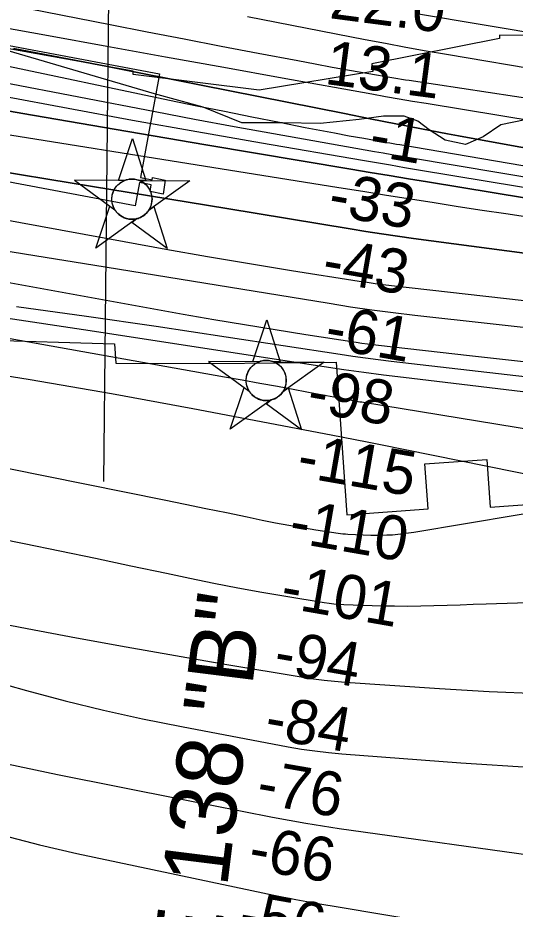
# Model space of a CAD drawing. Extents: x 3508733 to 3546731, y 546897 to 572481.
# Drawn here: x 3524097 to 3524852, y 564701 to 566055 of the extents above; entities that cross this region are included whole.
import ezdxf

# ---------------------------------------------------------------- set-up
doc = ezdxf.new("R2010")
doc.units = 0
for name, color, linetype in [('V-CHAN-DOCK', 7, 'Continuous'), ('V-CHAN-NAID', 7, 'Continuous'), ('V-RIVR-EDGE', 7, 'Continuous'), ('V-RIVR-RANG', 7, 'Continuous'), ('V-RRAP-RVMT', 7, 'Continuous'), ('V-TOPO-DPTH', 7, 'Continuous'), ('V-TOPO-MAJR', 7, 'Continuous'), ('V-TOPO-MINR', 7, 'Continuous'), ('V-TOPO-WATR', 7, 'Continuous')]:
    doc.layers.add(name, color=color, linetype=linetype)

msp = doc.modelspace()

# ---------------------------------------------------------------- linework, layer by layer
at = {"layer": 'V-CHAN-DOCK'}
for points in [[(3523879.2, 566051.2), (3524312, 565969.5), (3524282.8, 565812.2), (3524282.8, 565812.2)], [(3524282.8, 565812.2), (3524300.6, 565808.9), (3524301.1, 565812), (3524320.5, 565808.2), (3524317.3, 565786.7), (3524297.5, 565790.7), (3524299.3, 565801), (3524281.4, 565804.4), (3524281.4, 565804.4), (3524274.9, 565769.4), (3523635.2, 565889.5)]]:
    msp.add_lwpolyline(points, dxfattribs=at)
at = {"layer": 'V-CHAN-NAID'}
for points in [[(3524259.1, 565807.8), (3524249.5, 565807.9), (3524270.7, 565871.4), (3524290.9, 565807.6), (3524281.3, 565807.6), (3524279.7, 565808.2), (3524277.6, 565808.8), (3524275.6, 565809.3), (3524273.6, 565809.6), (3524272.4, 565809.7), (3524270.9, 565809.8), (3524269.1, 565809.8), (3524267.8, 565809.7), (3524265.9, 565809.5), (3524264.5, 565809.3), (3524262.7, 565808.9), (3524261.2, 565808.5), (3524260.1, 565808.2)], [(3524259.1, 565807.8), (3524182.6, 565808.3), (3524244.2, 565762.9), (3524243.1, 565764.9), (3524242.3, 565766.5), (3524241.5, 565768.4), (3524240.8, 565770.5), (3524240.4, 565771.8), (3524240, 565773.4), (3524239.8, 565774.9), (3524239.6, 565776.5), (3524239.5, 565778.2), (3524239.5, 565779.8), (3524239.6, 565781.9), (3524239.8, 565783.5), (3524240.2, 565785.7), (3524240.6, 565787.6), (3524241.2, 565789.5), (3524241.9, 565791.2), (3524242.6, 565792.8), (3524243.4, 565794.3), (3524244.5, 565796.1), (3524245.5, 565797.5), (3524246.5, 565798.8), (3524247.5, 565799.9), (3524248.8, 565801.3), (3524249.9, 565802.2), (3524251.6, 565803.6), (3524252.8, 565804.5), (3524254.5, 565805.6), (3524256.2, 565806.5), (3524257.7, 565807.2)], [(3524281.3, 565807.6), (3524357.8, 565807.1), (3524295.6, 565762.6), (3524296.5, 565764.1), (3524297.5, 565765.9), (3524298.2, 565767.5), (3524298.9, 565769.5), (3524299.5, 565771.2), (3524299.9, 565772.9), (3524300.2, 565774.9), (3524300.4, 565776.5), (3524300.6, 565778.7), (3524300.5, 565780.7), (3524300.3, 565782.9), (3524300.1, 565784.7), (3524299.6, 565786.9), (3524298.9, 565789.1), (3524298.2, 565791.1), (3524297.5, 565792.5), (3524296.5, 565794.4), (3524295.5, 565796.1), (3524294.3, 565797.8), (3524293, 565799.4), (3524291.7, 565800.7), (3524290.1, 565802.3), (3524288.3, 565803.7), (3524286.7, 565804.9), (3524284.8, 565806), (3524283.3, 565806.8)], [(3524277.6, 565749.7), (3524215.4, 565705.1), (3524236.5, 565768.6), (3524244.2, 565762.9), (3524244.8, 565762), (3524246.2, 565760.1), (3524247.4, 565758.7), (3524248.9, 565757.2), (3524250.3, 565755.9), (3524251.7, 565754.8), (3524253.1, 565753.8), (3524254.8, 565752.8), (3524256.5, 565751.9), (3524258.3, 565751), (3524259.8, 565750.5), (3524261.4, 565750), (3524263.6, 565749.4), (3524265.2, 565749.1), (3524267.2, 565748.9), (3524268.7, 565748.8), (3524270.6, 565748.7), (3524272.3, 565748.8), (3524274, 565749), (3524275.9, 565749.3)], [(3524295.6, 565762.6), (3524303.4, 565768.2), (3524323.6, 565704.4), (3524269.8, 565744.1), (3524277.6, 565749.7), (3524279.2, 565750.1), (3524280.8, 565750.7), (3524283, 565751.6), (3524284.7, 565752.5), (3524286.6, 565753.6), (3524288.3, 565754.8), (3524289.9, 565756.1), (3524291.2, 565757.2), (3524292.6, 565758.7), (3524293.8, 565760.1), (3524294.9, 565761.5)], [(3524462.9, 565532.4), (3524453.3, 565532.5), (3524474.5, 565596), (3524494.7, 565532.2), (3524485.1, 565532.3), (3524483.5, 565532.8), (3524481.4, 565533.5), (3524479.4, 565533.9), (3524477.3, 565534.2), (3524476.2, 565534.3), (3524474.6, 565534.4), (3524472.9, 565534.4), (3524471.6, 565534.4), (3524469.6, 565534.1), (3524468.3, 565533.9), (3524466.5, 565533.5), (3524465, 565533.1), (3524463.9, 565532.8)], [(3524462.9, 565532.4), (3524386.4, 565533), (3524448, 565487.6), (3524446.9, 565489.5), (3524446.1, 565491.1), (3524445.2, 565493.1), (3524444.6, 565495.1), (3524444.2, 565496.5), (3524443.8, 565498.1), (3524443.6, 565499.5), (3524443.4, 565501.1), (3524443.3, 565502.9), (3524443.3, 565504.4), (3524443.4, 565506.5), (3524443.6, 565508.1), (3524444, 565510.3), (3524444.4, 565512.3), (3524445, 565514.1), (3524445.7, 565515.8), (3524446.4, 565517.4), (3524447.2, 565518.9), (3524448.3, 565520.7), (3524449.3, 565522.2), (3524450.3, 565523.4), (3524451.3, 565524.6), (3524452.6, 565525.9), (3524453.7, 565526.9), (3524455.4, 565528.3), (3524456.6, 565529.1), (3524458.3, 565530.2), (3524460, 565531.2), (3524461.5, 565531.8)], [(3524485.1, 565532.3), (3524561.6, 565531.7), (3524499.4, 565487.2), (3524500.3, 565488.7), (3524501.3, 565490.5), (3524502, 565492.1), (3524502.7, 565494.1), (3524503.3, 565495.9), (3524503.7, 565497.5), (3524504, 565499.5), (3524504.2, 565501.1), (3524504.3, 565503.3), (3524504.3, 565505.4), (3524504.1, 565507.6), (3524503.9, 565509.3), (3524503.4, 565511.6), (3524502.7, 565513.7), (3524502, 565515.7), (3524501.3, 565517.1), (3524500.3, 565519), (3524499.3, 565520.8), (3524498, 565522.5), (3524496.8, 565524), (3524495.5, 565525.4), (3524493.9, 565526.9), (3524492.1, 565528.3), (3524490.5, 565529.5), (3524488.6, 565530.6), (3524487.1, 565531.4)], [(3524481.4, 565474.3), (3524419.2, 565429.8), (3524440.3, 565493.3), (3524448, 565487.6), (3524448.6, 565486.6), (3524450, 565484.7), (3524451.2, 565483.3), (3524452.7, 565481.8), (3524454.1, 565480.6), (3524455.5, 565479.4), (3524456.9, 565478.4), (3524458.6, 565477.4), (3524460.3, 565476.5), (3524462.1, 565475.7), (3524463.6, 565475.1), (3524465.2, 565474.6), (3524467.4, 565474), (3524469, 565473.7), (3524471, 565473.5), (3524472.5, 565473.4), (3524474.4, 565473.4), (3524476.1, 565473.4), (3524477.8, 565473.6), (3524479.7, 565473.9)], [(3524499.4, 565487.2), (3524507.2, 565492.8), (3524527.4, 565429), (3524473.6, 565468.7), (3524481.4, 565474.3), (3524483, 565474.8), (3524484.6, 565475.3), (3524486.8, 565476.2), (3524488.5, 565477.1), (3524490.4, 565478.2), (3524492.1, 565479.5), (3524493.7, 565480.7), (3524495, 565481.9), (3524496.4, 565483.3), (3524497.6, 565484.7), (3524498.7, 565486.2)]]:
    msp.add_lwpolyline(points, close=True, dxfattribs=at)
for centre in [(3524270, 565779.3), (3524473.8, 565503.9)]:
    msp.add_circle(centre, 30.5, dxfattribs=at)
at = {"layer": 'V-RIVR-EDGE'}
msp.add_lwpolyline([(3524866.8, 565900), (3524830, 565892.2), (3524803, 565873.9), (3524776, 565862.3), (3524745.4, 565869.1), (3524721, 565884.5), (3524703.8, 565898), (3524683, 565905.4), (3524651.8, 565905.5), (3524615, 565900.1), (3524555.5, 565894.1), (3524498.6, 565895.4), (3524436.7, 565895), (3524377.9, 565919), (3524304.4, 565939.4), (3524064.4, 566009.9)], dxfattribs=at)
at = {"layer": 'V-RIVR-RANG'}
msp.add_line((3524237, 566350.7), (3524226.6, 565350.7), dxfattribs=at)
at = {"layer": 'V-RRAP-RVMT'}
for points in [[(3524827.9, 566028.5), (3524827.9, 566023.4), (3524634, 565985), (3524635.4, 565973.3), (3524463.2, 565944.8), (3524271.9, 565968.7), (3524271.9, 565973.6), (3524074.8, 566009.4)], [(3526258.3, 565752.8), (3526053.8, 565759.9), (3526054, 565771.3), (3525840.3, 565785.2), (3525840.4, 565782.7), (3525643.5, 565821.3), (3525642.9, 565837.2), (3525438.8, 565876.6), (3525439.3, 565914.1), (3525237.3, 565952.4), (3525238.2, 565977.9), (3525037.5, 566014.9), (3525037.3, 566027), (3524827.9, 566028.5)], [(3524038.9, 565565.7), (3524243.4, 565559.8), (3524245.6, 565530.1), (3524394.8, 565529.7), (3524579.8, 565531.5)], [(3524579.8, 565531.5), (3524596, 565300), (3524719.8, 565308.8), (3524714.7, 565377.5), (3524808.7, 565384), (3524813.6, 565311.3), (3524953.5, 565321.4)]]:
    msp.add_lwpolyline(points, dxfattribs=at)
at = {"layer": 'V-TOPO-DPTH'}
for points in [[(3525130.5, 565892.5), (3524690.7, 565959.3), (3524685, 565960.2), (3524679.2, 565961.1), (3524673.5, 565962), (3524667.7, 565963), (3524626.6, 565970.2), (3524600.4, 565974.8), (3524574.1, 565979.5), (3524547.9, 565984.3), (3524521.6, 565989.2), (3524461.7, 566000.6), (3524405.5, 566011.4), (3524349.3, 566022.2), (3524293.2, 566033.1), (3524237.1, 566044.2), (3523968, 566097.4)], [(3524090.1, 566008.2), (3524232.7, 565980.7), (3524375.2, 565952.6), (3524592.4, 565909.2), (3524631.5, 565901.4), (3524670.6, 565893.8), (3524709.7, 565886.2), (3524748.8, 565878.7), (3524765.4, 565875.5), (3524812.9, 565866.7), (3524860.4, 565858.2), (3524908, 565850.3), (3524955.7, 565842.6), (3525771.7, 565716.3), (3525806.4, 565711.2), (3525841, 565706.3), (3525875.8, 565701.8), (3525910.6, 565697.6), (3526934.8, 565580.1)], [(3524090.1, 566008.2), (3524232.7, 565980.7), (3524375.2, 565952.6), (3524592.4, 565909.2), (3524631.5, 565901.4), (3524670.6, 565893.8), (3524709.7, 565886.2), (3524748.8, 565878.7), (3524765.4, 565875.5), (3524812.9, 565866.7), (3524860.4, 565858.2), (3524908, 565850.3), (3524955.7, 565842.6), (3525771.7, 565716.3), (3525806.4, 565711.2), (3525841, 565706.3), (3525875.8, 565701.8), (3525910.6, 565697.6), (3526934.8, 565580.1)], [(3526199.5, 565611.7), (3526108.1, 565622.7), (3526016.7, 565633.7), (3525854.1, 565653.3), (3525844, 565654.6), (3525833.8, 565655.9), (3525823.7, 565657.3), (3525813.6, 565658.8), (3525680.8, 565678.7), (3525604.4, 565690.4), (3525527.9, 565702.3), (3525451.6, 565714.7), (3525375.3, 565727.3), (3524691, 565842.3), (3524677.7, 565844.5), (3524664.5, 565846.8), (3524651.2, 565849.1), (3524638, 565851.4), (3524544.6, 565867.7), (3524484.7, 565878.3), (3524424.9, 565889.1), (3524365.1, 565900.3), (3524305.3, 565911.7), (3524073.4, 565956.4)], [(3526199.5, 565611.7), (3526108.1, 565622.7), (3526016.7, 565633.7), (3525854.1, 565653.3), (3525844, 565654.6), (3525833.8, 565655.9), (3525823.7, 565657.3), (3525813.6, 565658.8), (3525680.8, 565678.7), (3525604.4, 565690.4), (3525527.9, 565702.3), (3525451.6, 565714.7), (3525375.3, 565727.3), (3524691, 565842.3), (3524677.7, 565844.5), (3524664.5, 565846.8), (3524651.2, 565849.1), (3524638, 565851.4), (3524544.6, 565867.7), (3524484.7, 565878.3), (3524424.9, 565889.1), (3524365.1, 565900.3), (3524305.3, 565911.7), (3524073.4, 565956.4)], [(3523965.3, 565933.5), (3524104.2, 565909.3), (3524243.2, 565885.4), (3524382.2, 565861.8), (3524602.2, 565824.7), (3524631.3, 565819.8), (3524660.4, 565815), (3524689.5, 565810.2), (3524718.6, 565805.4), (3524918, 565772.9), (3525046.9, 565752.2), (3525175.8, 565731.9), (3525304.8, 565712.1), (3525433.9, 565692.7), (3525788.5, 565640.1), (3525809.6, 565637), (3525830.7, 565634.1), (3525851.8, 565631.3), (3525872.9, 565628.6), (3526418, 565561.4)], [(3523965.3, 565933.5), (3524104.2, 565909.3), (3524243.2, 565885.4), (3524382.2, 565861.8), (3524602.2, 565824.7), (3524631.3, 565819.8), (3524660.4, 565815), (3524689.5, 565810.2), (3524718.6, 565805.4), (3524918, 565772.9), (3525046.9, 565752.2), (3525175.8, 565731.9), (3525304.8, 565712.1), (3525433.9, 565692.7), (3525788.5, 565640.1), (3525809.6, 565637), (3525830.7, 565634.1), (3525851.8, 565631.3), (3525872.9, 565628.6), (3526418, 565561.4)], [(3526777.2, 565489.4), (3525892.5, 565602.7), (3525860, 565607), (3525827.5, 565611.4), (3525795, 565615.9), (3525762.5, 565620.6), (3524873.8, 565751.4), (3524837.6, 565756.8), (3524801.3, 565762.3), (3524765.1, 565767.9), (3524728.9, 565773.5), (3524692.7, 565779.2), (3524656.5, 565785), (3524620.3, 565790.7), (3524584.1, 565796.5), (3523856.5, 565912.8)], [(3526777.2, 565489.4), (3525892.5, 565602.7), (3525860, 565607), (3525827.5, 565611.4), (3525795, 565615.9), (3525762.5, 565620.6), (3524873.8, 565751.4), (3524837.6, 565756.8), (3524801.3, 565762.3), (3524765.1, 565767.9), (3524728.9, 565773.5), (3524692.7, 565779.2), (3524656.5, 565785), (3524620.3, 565790.7), (3524584.1, 565796.5), (3523856.5, 565912.8)], [(3524061.9, 565823), (3524179.4, 565803.7), (3524296.8, 565784.4), (3524414.2, 565765), (3524601, 565734), (3524625, 565730.2), (3524649, 565726.5), (3524673, 565723), (3524697.1, 565719.7), (3525623.5, 565596.8), (3525656.6, 565592.5), (3525689.6, 565588.4), (3525722.7, 565584.4), (3525755.8, 565580.6), (3525787.7, 565577.1), (3525804.8, 565575.1), (3525822, 565573.1), (3525839.1, 565571.1), (3525856.3, 565569.1), (3525873.4, 565567), (3525890.6, 565564.8), (3525907.7, 565562.6), (3525924.8, 565560.4), (3527000.1, 565416.8)], [(3524061.9, 565823), (3524179.4, 565803.7), (3524296.8, 565784.4), (3524414.2, 565765), (3524601, 565734), (3524625, 565730.2), (3524649, 565726.5), (3524673, 565723), (3524697.1, 565719.7), (3525623.5, 565596.8), (3525656.6, 565592.5), (3525689.6, 565588.4), (3525722.7, 565584.4), (3525755.8, 565580.6), (3525787.7, 565577.1), (3525804.8, 565575.1), (3525822, 565573.1), (3525839.1, 565571.1), (3525856.3, 565569.1), (3525873.4, 565567), (3525890.6, 565564.8), (3525907.7, 565562.6), (3525924.8, 565560.4), (3527000.1, 565416.8)]]:
    msp.add_lwpolyline(points, dxfattribs=at)
at = {"layer": 'V-TOPO-MAJR'}
for points in [[(3526752.2, 565406.9), (3525858.3, 565516.2), (3525836.4, 565518.9), (3525814.6, 565521.4), (3525792.7, 565523.9), (3525770.8, 565526.3), (3525317.9, 565574.9), (3525204.8, 565587.1), (3525091.6, 565599.5), (3524978.5, 565612.1), (3524865.4, 565624.8), (3524663.9, 565647.6), (3524651.5, 565649.1), (3524639.2, 565650.7), (3524626.9, 565652.5), (3524614.7, 565654.3), (3524512, 565670.7), (3524448.4, 565681.1), (3524384.9, 565691.8), (3524321.5, 565702.9), (3524258.1, 565714.3), (3523785.6, 565800.9)], [(3525548.4, 565318.8), (3524621.5, 565470.3), (3524618.8, 565470.8), (3524616.1, 565471.2), (3524613.4, 565471.7), (3524610.6, 565472.2), (3524593.5, 565475.4), (3524582.2, 565477.5), (3524570.9, 565479.6), (3524559.6, 565481.7), (3524548.4, 565483.8), (3524517.4, 565489.6), (3524490.7, 565494.6), (3524463.9, 565499.5), (3524437.2, 565504.4), (3524410.4, 565509.2), (3523835.7, 565611.6)], [(3523876, 565302.9), (3524106.6, 565256.1), (3524160.6, 565245), (3524214.6, 565233.9), (3524268.5, 565222.6), (3524322.5, 565211.2), (3524357.9, 565203.6), (3524394.1, 565196.2), (3524430.5, 565189.1), (3524466.9, 565182.5), (3524503.4, 565176.3), (3524561.8, 565166.7), (3524569.2, 565165.7), (3524576.6, 565164.8), (3524584, 565164.2), (3524591.5, 565163.8), (3524648.8, 565161.9), (3524668.7, 565161.4), (3524688.6, 565161.2), (3524708.5, 565161.5), (3524728.3, 565162), (3524748.2, 565162.7), (3524768.1, 565163.4), (3524787.9, 565164.1), (3524807.8, 565164.7), (3524997.8, 565170.7)]]:
    msp.add_lwpolyline(points, dxfattribs=at)
at = {"layer": 'V-TOPO-MINR'}
for points in [[(3526216.7, 565702.4), (3526093.4, 565717), (3525876.1, 565742.2), (3525861.4, 565744), (3525846.7, 565745.9), (3525832.1, 565747.9), (3525817.4, 565750), (3525617.9, 565779.5), (3525503.6, 565796.8), (3525389.3, 565814.3), (3525275.1, 565832.5), (3525161, 565851), (3524716.6, 565924.4), (3524696, 565927.8), (3524675.4, 565931.3), (3524654.8, 565934.9), (3524634.2, 565938.6), (3524498, 565963.2), (3524409.4, 565979.2), (3524320.7, 565995.2), (3524232.1, 566011.2), (3524143.4, 566027.2), (3523550, 566134.5)], [(3525130.5, 565892.5), (3524690.7, 565959.3), (3524685, 565960.2), (3524679.2, 565961.1), (3524673.5, 565962), (3524667.7, 565963), (3524626.6, 565970.2), (3524600.4, 565974.8), (3524574.1, 565979.5), (3524547.9, 565984.3), (3524521.6, 565989.2), (3524461.7, 566000.6), (3524405.5, 566011.4), (3524349.3, 566022.2), (3524293.2, 566033.1), (3524237.1, 566044.2), (3523968, 566097.4)], [(3526265.4, 565861.3), (3526102.8, 565857.8), (3526075.3, 565857.4), (3526047.8, 565857.4), (3526020.4, 565857.9), (3525992.9, 565858.8), (3525974.9, 565859.5), (3525956.4, 565860.5), (3525938, 565861.6), (3525919.5, 565863.1), (3525901.1, 565864.8), (3525869.8, 565867.9), (3525867.1, 565868.2), (3525864.3, 565868.5), (3525861.5, 565868.9), (3525858.8, 565869.3), (3525817.1, 565875.2), (3525793.5, 565878.6), (3525770, 565882.2), (3525746.4, 565885.9), (3525722.9, 565889.8), (3524701.7, 566060.7)], [(3526269.8, 565792.1), (3526133, 565806.1), (3525899.4, 565830.1), (3525879.4, 565832.2), (3525859.4, 565834.5), (3525839.5, 565837), (3525819.5, 565839.7), (3525338.4, 565905.9), (3525229.3, 565921.5), (3525120.3, 565937.7), (3525011.5, 565954.9), (3524902.8, 565972.7), (3524747.4, 565999), (3524716.4, 566004.3), (3524685.5, 566009.8), (3524654.6, 566015.5), (3524623.8, 566021.4), (3524445.2, 566056)], [(3525627.7, 565699.4), (3524676.6, 565861.6), (3524671.6, 565862.5), (3524666.6, 565863.4), (3524661.6, 565864.2), (3524656.6, 565865.1), (3524622, 565871.2), (3524599.7, 565875.2), (3524577.4, 565879.3), (3524555.1, 565883.5), (3524532.8, 565887.8), (3524493.8, 565895.5), (3524452, 565903.8), (3524410.3, 565912.2), (3524368.5, 565920.7), (3524326.9, 565929.4), (3524063, 565984.6)], [(3526199.5, 565611.7), (3526108.1, 565622.7), (3526016.7, 565633.7), (3525854.1, 565653.3), (3525844, 565654.6), (3525833.8, 565655.9), (3525823.7, 565657.3), (3525813.6, 565658.8), (3525680.8, 565678.7), (3525604.4, 565690.4), (3525527.9, 565702.3), (3525451.6, 565714.7), (3525375.3, 565727.3), (3524691, 565842.3), (3524677.7, 565844.5), (3524664.5, 565846.8), (3524651.2, 565849.1), (3524638, 565851.4), (3524544.6, 565867.7), (3524484.7, 565878.3), (3524424.9, 565889.1), (3524365.1, 565900.3), (3524305.3, 565911.7), (3524073.4, 565956.4)], [(3526418, 565561.4), (3525872.9, 565628.6), (3525851.8, 565631.3), (3525830.7, 565634.1), (3525809.6, 565637), (3525788.5, 565640.1), (3525433.9, 565692.7), (3525304.8, 565712.1), (3525175.8, 565731.9), (3525046.9, 565752.2), (3524918, 565772.9), (3524718.6, 565805.4), (3524689.5, 565810.2), (3524660.4, 565815), (3524631.3, 565819.8), (3524602.2, 565824.7), (3524382.2, 565861.8), (3524243.2, 565885.4), (3524104.2, 565909.3), (3523965.3, 565933.5)], [(3526265.5, 565592), (3526121.1, 565609.6), (3525863.5, 565641), (3525847.9, 565642.9), (3525832.3, 565645), (3525816.7, 565647.2), (3525801.1, 565649.4), (3525593.2, 565680.4), (3525473.8, 565698.6), (3525354.4, 565717.1), (3525235.1, 565736.1), (3525115.8, 565755.6), (3524705, 565823.6), (3524683.7, 565827.1), (3524662.4, 565830.7), (3524641.1, 565834.3), (3524619.9, 565837.9), (3524466.5, 565864.4), (3524368.6, 565881.5), (3524270.8, 565899), (3524173, 565916.8), (3524075.3, 565935)], [(3526777.2, 565489.4), (3525892.5, 565602.7), (3525860, 565607), (3525827.5, 565611.4), (3525795, 565615.9), (3525762.5, 565620.6), (3524873.8, 565751.4), (3524837.6, 565756.8), (3524801.3, 565762.3), (3524765.1, 565767.9), (3524728.9, 565773.5), (3524692.7, 565779.2), (3524656.5, 565785), (3524620.3, 565790.7), (3524584.1, 565796.5), (3523856.5, 565912.8)], [(3527000.1, 565416.8), (3525924.8, 565560.4), (3525907.7, 565562.6), (3525890.6, 565564.8), (3525873.4, 565567), (3525856.3, 565569.1), (3525839.1, 565571.1), (3525822, 565573.1), (3525804.8, 565575.1), (3525787.7, 565577.1), (3525755.8, 565580.6), (3525722.7, 565584.4), (3525689.6, 565588.4), (3525656.6, 565592.5), (3525623.5, 565596.8), (3524697.1, 565719.7), (3524673, 565723), (3524649, 565726.5), (3524625, 565730.2), (3524601, 565734), (3524414.2, 565765), (3524296.8, 565784.4), (3524179.4, 565803.7), (3524061.9, 565823)], [(3526994.3, 565326), (3525908.3, 565467.4), (3525891.7, 565469.5), (3525875.1, 565471.6), (3525858.5, 565473.7), (3525841.8, 565475.8), (3525810.6, 565479.8), (3525806.6, 565480.2), (3525792.4, 565481.7), (3525784.4, 565482.6), (3525776.3, 565483.5), (3525768.2, 565484.3), (3525760.1, 565485.2), (3524699.2, 565602.8), (3524666.6, 565606.6), (3524634.1, 565610.8), (3524601.6, 565615.5), (3524569.2, 565620.6), (3524229.2, 565676), (3524107.1, 565695.9), (3523985, 565715.6)], [(3527023.7, 565262.5), (3525853, 565423.4), (3525827.2, 565426.8), (3525801.5, 565430), (3525775.7, 565433.1), (3525749.9, 565436), (3525092.3, 565507.1), (3525014.8, 565515.5), (3524937.3, 565524.1), (3524859.8, 565532.7), (3524782.3, 565541.4), (3524644.4, 565557), (3524635.9, 565558), (3524627.4, 565559.1), (3524618.9, 565560.2), (3524610.5, 565561.5), (3524534.1, 565573.2), (3524487.4, 565580.6), (3524440.8, 565588.2), (3524394.3, 565596.1), (3524347.8, 565604.3), (3524035.5, 565660.7)], [(3526174.6, 565349), (3526049, 565367.6), (3525822.9, 565400.5), (3525810.3, 565402.3), (3525797.7, 565404), (3525785.1, 565405.5), (3525772.5, 565407), (3525576.6, 565428.7), (3525466, 565441), (3525355.5, 565453.4), (3525245, 565466), (3525134.4, 565478.6), (3524663.2, 565532.9), (3524643.9, 565535.3), (3524624.7, 565537.7), (3524605.4, 565540.4), (3524586.2, 565543.3), (3524412.8, 565569.9), (3524306.9, 565585.8), (3524200.9, 565601.1), (3524094.8, 565615.7)], [(3526277.8, 565261.6), (3525845.5, 565361.9), (3525819.4, 565367.5), (3525793.2, 565372.7), (3525766.9, 565377), (3525740.5, 565380.9), (3525714, 565384.3), (3525687.5, 565387.7), (3525661, 565391), (3525634.5, 565394.2), (3524682.2, 565508.3), (3524652, 565512.1), (3524621.9, 565516), (3524591.7, 565520.3), (3524561.6, 565524.8), (3524196.3, 565581), (3524078.5, 565598.7)], [(3524681.4, 565271.3), (3524689.5, 565272.3), (3524697.6, 565273.6), (3524933.2, 565313), (3524939.4, 565317.1), (3524942.9, 565321.9), (3524942.3, 565327.8), (3524938.9, 565334.4), (3524928.3, 565342), (3524917, 565348.5), (3524904.9, 565353.2), (3524892.3, 565356.7), (3524644.8, 565406.8), (3524626.8, 565410.4), (3524608.7, 565413.9), (3524590.6, 565417.5), (3524572.5, 565420.9), (3524362.4, 565460.8), (3524239.1, 565483.4), (3524115.6, 565504.8), (3523991.8, 565524.5)], [(3523962.3, 565394.4), (3524319, 565322.6), (3524350.6, 565316.2), (3524382.1, 565309.7), (3524413.6, 565303.2), (3524445.1, 565296.7), (3524467.5, 565292), (3524487.8, 565287.9), (3524508.2, 565284), (3524528.7, 565280.5), (3524549.2, 565277.2), (3524582.8, 565272), (3524586.6, 565271.5), (3524590.3, 565271.1), (3524594, 565270.8), (3524597.8, 565270.6), (3524632.7, 565269.2), (3524640.8, 565269), (3524649, 565269), (3524657.1, 565269.3), (3524665.2, 565269.7), (3524673.3, 565270.4), (3524681.4, 565271.3)], [(3523612, 565222.8), (3524111.1, 565127.2), (3524186, 565113.1), (3524261, 565099.4), (3524336, 565086.2), (3524411.2, 565073.3), (3524529.8, 565053.4), (3524545.7, 565051), (3524561.6, 565048.8), (3524577.6, 565047.2), (3524593.7, 565045.8), (3524736.9, 565035.9), (3524812.3, 565031.6), (3524887.7, 565028.5)], [(3524051.7, 565049.1), (3524110, 565033.1), (3524168.4, 565017.6), (3524227, 565003.1), (3524286, 564990.2), (3524345.2, 564978.2), (3524507.3, 564947.7), (3524527.5, 564944.2), (3524547.8, 564941.2), (3524568.2, 564938.8), (3524588.6, 564937), (3524769.3, 564923.3), (3524880.2, 564915.9)], [(3524063.3, 564925.1), (3524157.2, 564905.6), (3524251.2, 564886.5), (3524345.3, 564867.8), (3524483.3, 564840.7), (3524508.5, 564836), (3524533.7, 564831.5), (3524559, 564827.5), (3524584.3, 564823.7), (3525239.3, 564732.3), (3525314.8, 564721.8), (3525390.3, 564711.2), (3525465.9, 564700.6)], [(3524073.7, 564813.2), (3524129.9, 564798.8), (3524186.4, 564785.6), (3524452, 564729.1), (3524485.4, 564722.2), (3524518.8, 564715.7), (3524552.2, 564709.6), (3524585.8, 564703.8), (3524709.4, 564683.2)]]:
    msp.add_lwpolyline(points, dxfattribs=at)
at = {"layer": 'V-TOPO-WATR'}
msp.add_lwpolyline([(3526934.8, 565580.1), (3525910.6, 565697.6), (3525875.8, 565701.8), (3525841, 565706.3), (3525806.4, 565711.2), (3525771.7, 565716.3), (3524955.7, 565842.6), (3524908, 565850.3), (3524860.4, 565858.2), (3524812.9, 565866.7), (3524765.4, 565875.5), (3524748.8, 565878.7), (3524709.7, 565886.2), (3524670.6, 565893.8), (3524631.5, 565901.4), (3524592.4, 565909.2), (3524375.2, 565952.6), (3524232.7, 565980.7), (3524090.1, 566008.2)], dxfattribs=at)

# ---------------------------------------------------------------- texts
at = {"layer": 'V-CHAN-NAID'}
msp.add_text('MILE 138 "B"', height=100, rotation=82.875, dxfattribs=at).set_placement((3524371, 564386.5))
at = {"layer": 'V-RIVR-RANG'}
for s, rotation, p in [('22.0', 352.5183, (3524568.5, 566054.4)), ('13.1', 352.5183, (3524561, 565954.5)), ('-1', 350.1392, (3524627.4, 565846.5)), ('-33', 350.1392, (3524565.5, 565755.8)), ('-43', 350.1392, (3524556.3, 565656)), ('-61', 350.1392, (3524560.4, 565553.9)), ('-98', 350.1392, (3524533.4, 565457.2)), ('-115', 350.1392, (3524518, 565358.5)), ('-110', 350.1392, (3524506, 565259.2)), ('-101', 350.1392, (3524493.2, 565160)), ('-94', 350.1392, (3524483, 565060.3)), ('-84', 350.1392, (3524469.2, 564961.3)), ('-76', 350.1392, (3524456.7, 564862.1)), ('-66', 350.1392, (3524444.4, 564762.9)), ('-56', 350.1392, (3524429.5, 564664))]:
    msp.add_text(s, height=67, rotation=rotation, dxfattribs=at).set_placement(p)

doc.saveas('drawing.dxf')
